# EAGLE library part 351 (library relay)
RELAY 2 x switch, Omron
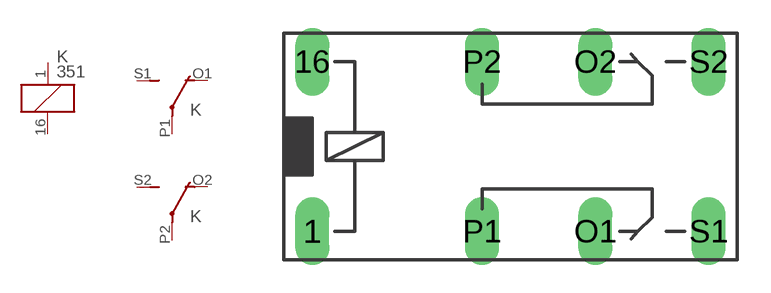
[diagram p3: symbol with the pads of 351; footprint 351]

Designator prefix K; gates 1=K 2=U 3=U

## 351 (OC_FARNELL: unknown; OC_NEWARK: unknown)  [351]
1  1:1  pas
16  1:2  pas
O1  2:O  pas
O2  3:O  pas
P1  2:P  pas
P2  3:P  pas
S1  2:S  pas
S2  3:S  pas

## Footprint 351 (pad centres in mm)
RELAY 2 x switch, same as G5 V-2, Omron
drill 1.016 long: 1 -3.81,-3.81; 16 -3.81,3.81; O1 8.89,-3.81; O2 8.89,3.81; P1 3.81,-3.81; P2 3.81,3.81; S1 13.97,-3.81; S2 13.97,3.81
